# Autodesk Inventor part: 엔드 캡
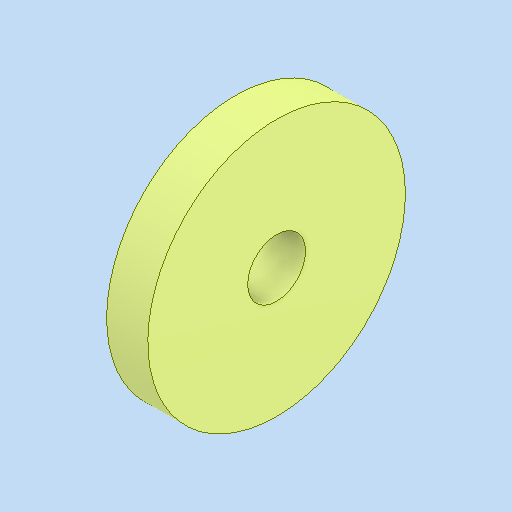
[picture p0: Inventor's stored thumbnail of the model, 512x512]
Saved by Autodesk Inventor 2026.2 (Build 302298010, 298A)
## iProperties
Created: 2026-03
Part Number: 엔드 캡
Material: 강철, 연강
Document SubType Name: Modeling
Designer: PC-2-06
Density: 7.85 g/cm^3
Appearance: 기본값
Author: jhkim
Sending System: Autodesk Inventor 2026
Preprocessor: ST-DEVELOPER v20.1
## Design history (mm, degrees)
feature "솔리드1"
node "솔리드2"
